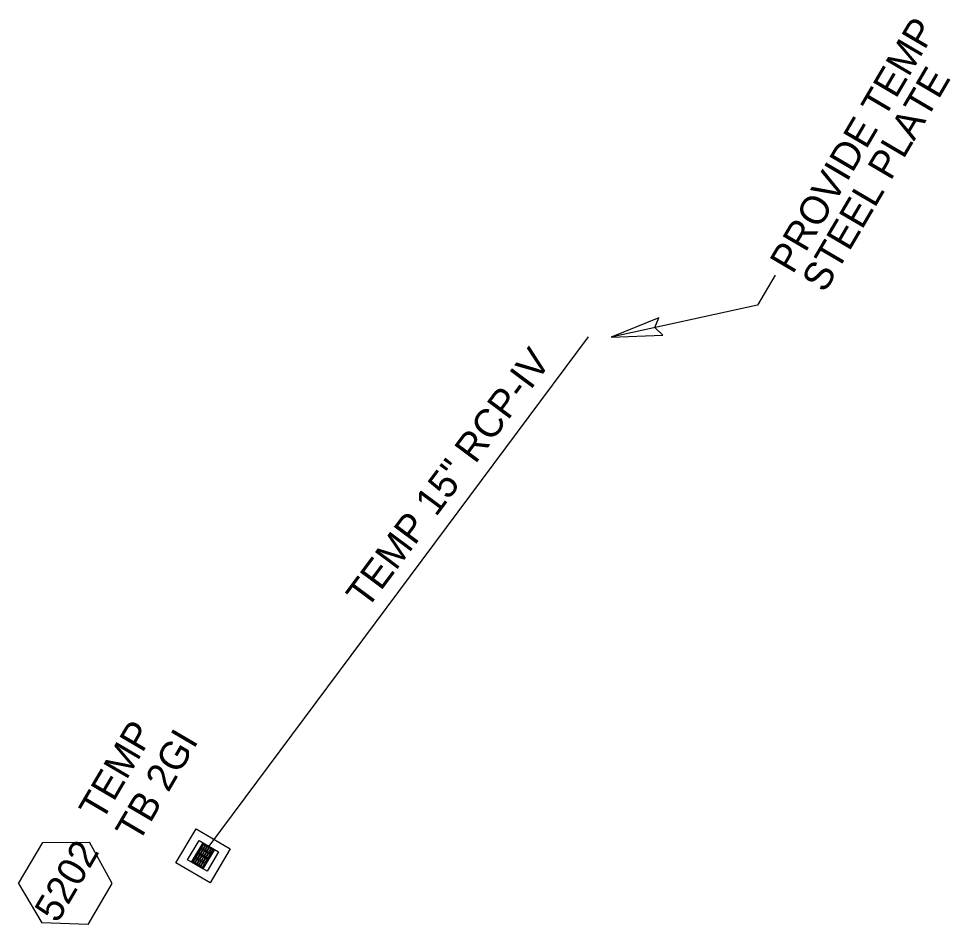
# Model space of a CAD drawing. Extents: x 2214419 to 2238519, y 983271 to 1015868.
# Drawn here: x 2232547.5 to 2232712.5, y 1005821.4 to 1005981.7 of the extents above; entities that cross this region are included whole.
import ezdxf

# ---------------------------------------------------------------- set-up
doc = ezdxf.new("R2010")
doc.units = 0
for name, color, linetype in [('Prop Drainage Structure Box Number Symbol CELL', 7, 'Continuous'), ('Prop Drainage Structure Drop Inlet Grate 2 Wide Slots and Sag Grates 840 22 TB CELL', 7, 'Continuous'), ('Prop Drainage Structure Drop Inlet Grate 2 Wide Slots and Sag Grates 840 22 TB Label', 7, 'Continuous'), ('Prop Drainage Structure Pipe RCP 15in Class IV', 7, 'Continuous'), ('Prop Drainage Structure Pipe RCP 15in Class IV Label', 7, 'Continuous'), ('Prop Drainage Structure Plot Symbol 20 Scale', 7, 'Continuous'), ('Prop Drainage Structure Plot Symbol 50 Scale', 7, 'Continuous'), ('Prop Plan Preparation Drainage Notes Label', 7, 'Continuous')]:
    doc.layers.add(name, color=color, linetype=linetype)

msp = doc.modelspace()

# ---------------------------------------------------------------- linework, layer by layer
at = {"layer": 'Prop Drainage Structure Box Number Symbol CELL'}
for p, q in [((2232547.47, 1005828.6), (2232551.73, 1005835.84)), ((2232551.73, 1005835.84), (2232560.04, 1005835.91)), ((2232564.03, 1005828.61), (2232560.04, 1005835.91)), ((2232547.47, 1005828.6), (2232551.58, 1005821.64)), ((2232559.78, 1005821.37), (2232564.03, 1005828.61)), ((2232559.78, 1005821.37), (2232551.58, 1005821.64))]:
    msp.add_line(p, q, dxfattribs=at)
at = {"layer": 'Prop Drainage Structure Drop Inlet Grate 2 Wide Slots and Sag Grates 840 22 TB CELL'}
for p, q in [((2232579.11, 1005834.09), (2232579.11, 1005834.09)), ((2232581.13, 1005835.23), (2232581.13, 1005835.23)), ((2232580.12, 1005833.5), (2232580.12, 1005833.5)), ((2232581.13, 1005832.91), (2232581.13, 1005832.91)), ((2232579.11, 1005831.78), (2232579.11, 1005831.78))]:
    msp.add_line(p, q, dxfattribs=at)
for points in [[(2232582.14, 1005834.64), (2232580.11, 1005831.19), (2232578.1, 1005832.37), (2232580.13, 1005835.82), (2232582.14, 1005834.64)], [(2232582.05, 1005834.61), (2232580.09, 1005831.27), (2232578.19, 1005832.39), (2232580.15, 1005835.73), (2232582.05, 1005834.61), (2232582.05, 1005834.61)], [(2232582.04, 1005834.61), (2232581.07, 1005832.96), (2232579.18, 1005834.07), (2232580.15, 1005835.72), (2232582.04, 1005834.61)], [(2232580.51, 1005835.41), (2232580.08, 1005834.7), (2232579.85, 1005834.83), (2232580.27, 1005835.55), (2232580.51, 1005835.41)], [(2232580.84, 1005835.22), (2232580.42, 1005834.5), (2232580.18, 1005834.64), (2232580.6, 1005835.36), (2232580.84, 1005835.22)], [(2232581.06, 1005832.94), (2232580.09, 1005831.29), (2232578.2, 1005832.4), (2232579.17, 1005834.05), (2232581.06, 1005832.94)], [(2232579.52, 1005833.74), (2232579.1, 1005833.03), (2232578.87, 1005833.16), (2232579.29, 1005833.88), (2232579.52, 1005833.74)], [(2232579.86, 1005833.55), (2232579.43, 1005832.83), (2232579.2, 1005832.97), (2232579.62, 1005833.69), (2232579.86, 1005833.55)], [(2232580.04, 1005834.62), (2232579.62, 1005833.91), (2232579.39, 1005834.04), (2232579.81, 1005834.76), (2232580.04, 1005834.62)], [(2232580.37, 1005834.43), (2232579.95, 1005833.71), (2232579.72, 1005833.85), (2232580.14, 1005834.57), (2232580.37, 1005834.43)], [(2232580.71, 1005834.23), (2232580.28, 1005833.52), (2232580.05, 1005833.65), (2232580.47, 1005834.37), (2232580.71, 1005834.23)], [(2232581.04, 1005834.04), (2232580.62, 1005833.32), (2232580.38, 1005833.46), (2232580.8, 1005834.18), (2232581.04, 1005834.04)], [(2232581.17, 1005835.02), (2232580.75, 1005834.31), (2232580.51, 1005834.44), (2232580.94, 1005835.16), (2232581.17, 1005835.02)], [(2232581.37, 1005833.84), (2232580.95, 1005833.12), (2232580.71, 1005833.26), (2232581.14, 1005833.98), (2232581.37, 1005833.84)], [(2232581.5, 1005834.83), (2232581.08, 1005834.11), (2232580.85, 1005834.25), (2232581.27, 1005834.97), (2232581.5, 1005834.83)], [(2232581.84, 1005834.63), (2232581.41, 1005833.91), (2232581.18, 1005834.05), (2232581.6, 1005834.77), (2232581.84, 1005834.63)], [(2232579.06, 1005832.95), (2232578.64, 1005832.24), (2232578.4, 1005832.37), (2232578.83, 1005833.09), (2232579.06, 1005832.95)], [(2232579.39, 1005832.76), (2232578.97, 1005832.04), (2232578.74, 1005832.18), (2232579.16, 1005832.9), (2232579.39, 1005832.76)], [(2232579.72, 1005832.56), (2232579.3, 1005831.84), (2232579.07, 1005831.98), (2232579.49, 1005832.7), (2232579.72, 1005832.56)], [(2232580.06, 1005832.37), (2232579.63, 1005831.65), (2232579.4, 1005831.79), (2232579.82, 1005832.51), (2232580.06, 1005832.37)], [(2232580.19, 1005833.35), (2232579.77, 1005832.64), (2232579.53, 1005832.77), (2232579.96, 1005833.49), (2232580.19, 1005833.35)], [(2232580.39, 1005832.17), (2232579.97, 1005831.45), (2232579.73, 1005831.59), (2232580.16, 1005832.31), (2232580.39, 1005832.17)], [(2232580.52, 1005833.16), (2232580.1, 1005832.44), (2232579.87, 1005832.58), (2232580.29, 1005833.3), (2232580.52, 1005833.16)], [(2232580.85, 1005832.96), (2232580.43, 1005832.24), (2232580.2, 1005832.38), (2232580.62, 1005833.1), (2232580.85, 1005832.96)]]:
    msp.add_lwpolyline(points, dxfattribs=at)
at = {"layer": 'Prop Drainage Structure Pipe RCP 15in Class IV'}
msp.add_line((2232648.34, 1005925.42), (2232581.13, 1005835.23), dxfattribs=at)
at = {"layer": 'Prop Drainage Structure Plot Symbol 20 Scale'}
msp.add_lwpolyline([(2232582.86, 1005834.21), (2232580.83, 1005830.77), (2232577.38, 1005832.79), (2232579.41, 1005836.24)], close=True, dxfattribs=at)
at = {"layer": 'Prop Drainage Structure Plot Symbol 50 Scale'}
msp.add_lwpolyline([(2232584.91, 1005834.75), (2232581.36, 1005828.71), (2232575.33, 1005832.26), (2232578.88, 1005838.29)], close=True, dxfattribs=at)
at = {"layer": 'Prop Plan Preparation Drainage Notes Label'}
for p, q in [((2232681.41, 1005936.3), (2232678.28, 1005930.98)), ((2232678.28, 1005930.98), (2232652.38, 1005925.37))]:
    msp.add_line(p, q, dxfattribs=at)
msp.add_lwpolyline([(2232660.84, 1005928.79), (2232652.38, 1005925.37), (2232661.56, 1005925.72), (2232660.1, 1005927.04)], close=True, dxfattribs=at)

# ---------------------------------------------------------------- texts
at = {"layer": 'Prop Drainage Structure Box Number Symbol CELL'}
msp.add_text('5202', height=5, rotation=59.5518, dxfattribs=at).set_placement((2232554.33, 1005821.43))
at = {"layer": 'Prop Drainage Structure Drop Inlet Grate 2 Wide Slots and Sag Grates 840 22 TB Label'}
for s, p in [('TEMP', (2232562.22, 1005839.42)), ('TB 2GI', (2232568.69, 1005835.62))]:
    msp.add_text(s, height=5, rotation=59.5518, dxfattribs=at).set_placement(p)
at = {"layer": 'Prop Drainage Structure Pipe RCP 15in Class IV Label'}
msp.add_text('TEMP 15" RCP-IV ', height=5, rotation=53.3066, dxfattribs=at).set_placement((2232609.15, 1005877.01))
at = {"layer": 'Prop Plan Preparation Drainage Notes Label'}
for s, p in [('PROVIDE TEMP', (2232684.55, 1005936.35)), ('STEEL PLATE', (2232690.21, 1005933.03))]:
    msp.add_text(s, height=5, rotation=59.566, dxfattribs=at).set_placement(p)

doc.saveas('drawing.dxf')
